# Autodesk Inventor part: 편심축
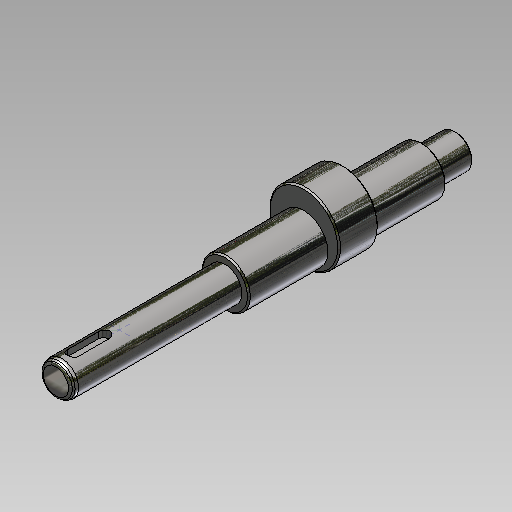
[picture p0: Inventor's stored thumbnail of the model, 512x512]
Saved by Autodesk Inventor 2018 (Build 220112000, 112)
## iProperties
Created: 2016-02
Part Number: 편심축
Material: 강철, 연강
Document SubType Name: Modeling
Designer: mduedu
Density: 1 g/cm^3
Appearance: 반광택
Author: mduedu
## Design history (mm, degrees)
sketch "스케치1"
  geometry: C1 r 6 at (0, 0); 1 further point
  constraints: 1 centre point, 1 coincident
  dimensions: "d0" = 12 diameter of C1
extrude "돌출1" new body sketch "스케치1" distance "d1" = 142; taper "d2" = 0 deg
chamfer "모따기1" distance "d3" = 0.5; stored, may be unused: second distance "d4" = 2, angle "d5" = 45 deg
node "작업 평면2"
sketch "스케치3"
  geometry: C1 r 8.5 at (0, 0); 1 further point
  constraints: 1 centre point, 1 coincident
  dimensions: "d12" = 17 diameter of C1
extrude "돌출3" join sketch "스케치3" distance "d13" = 70; taper "d14" = 0 deg
node "작업 평면3"
sketch "스케치4"
  geometry: L1 (0, 142)-(0, 0); L2 (-2, 136)-(-2, 125); L3 (2, 125)-(2, 136); L4 (6, 142)-(-6, 142) reference; A1 r 2 centre (0, 136) between (2, 136) and (-2, 136); A2 r 2 centre (0, 125) between (-2, 125) and (2, 125)
  constraints: 6 end point, 4 point on circle, 4 tangent, 2 centre point, 2 point on line, 1 midpoint, 1 parallel
  dimensions: "d15" = 4 distance between parallel lines of L2 L3; "d18" = 15 dimension on A2 A1; "d36" = 4 distance edge to line of A1 L4
extrude "돌출4" cut sketch "스케치4" distance "d19" = 2.5; taper "d20" = 0 deg
node "작업 평면1"
sketch "스케치2"
  geometry: C1 r 12.5 at (0, 3); C2 r 8.5 at (0, 0) reference; 1 further point
  constraints: 1 centre point, 1 vertical alignment
  dimensions: "d7" = 25 diameter of C1; "d32" = 3 distance of C1.centre point (0, 0)
extrude "돌출2" join sketch "스케치2" stored distance "d8" = 14; taper "d9" = 0 deg
sketch "스케치5"
  geometry: L1 (6, 82)-(6, 142) reference; L2 (-6, 82)-(-6, 142) reference; L3 (6, 115)-(-6, 115); L4 (6, 116.5)-(4.5, 115); L5 (6, 116.5)-(6, 115); L6 (4.5, 115)-(6, 115); L7 (6, 142)-(-6, 142) reference; 1 further point
  constraints: 8 end point, 4 point on line, 2 collinear, 1 perpendicular
  dimensions: "d22" = 3 diameter of L4.start L3; "d24" = 45 deg angle of L3 L4; "d37" = 27 distance between parallel lines of L7 L3
revolve "회전1" sketch "스케치5" stored, may be unused: angle "d25" = 90 deg
sketch "스케치6"
  geometry: L1 (6, 116.5)-(4.5, 115) reference; L2 (6, 113.5)-(4.5, 115) reference; 2 further points
  constraints: 1 coincident
node "작업 평면4"
chamfer "모따기2" distance "d33" = 0.5; stored, may be unused: second distance "d34" = 2, angle "d35" = 45 deg
sketch "스케치8"
  geometry: L1 (5.1, 142)-(6, 140.441); L2 (6, 82)-(6, 142) reference; L3 (6, 142)-(-6, 142) reference; L4 (0, 142)-(0, 86.696); 1 further point
  constraints: 4 end point, 2 point on line, 1 midpoint, 1 perpendicular
  dimensions: "d38" = 10.2 diameter of L1.start L4; "d43" = 30 deg angle of L2 L1
revolve "회전2" sketch "스케치8" stored, may be unused: angle "d45" = 90 deg
fillet "모깎기1" dims "d46" = 2, "d47" = 1
node "솔리드1"
other parameters: "d6" = -47, "d11" = -12, "d26" = 28
